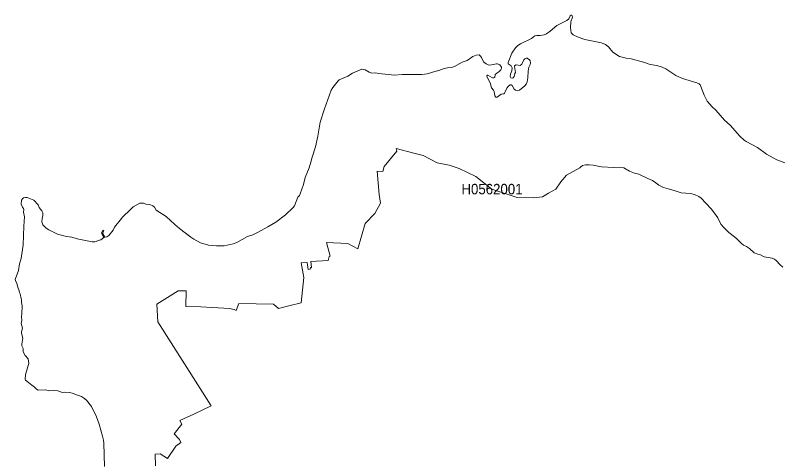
# Model space of a CAD drawing. Extents: x 369010 to 739155, y 6377141 to 6616555.
# Drawn here: x 484601 to 491944, y 6568141 to 6572404 of the extents above; entities that cross this region are included whole.
import ezdxf
from ezdxf.enums import TextEntityAlignment as Align

# ---------------------------------------------------------------- set-up
doc = ezdxf.new("R2010")
doc.units = 0
doc.header["$LTSCALE"] = 40
doc.layers.add('1', color=7, linetype='Continuous', lineweight=13)
doc.layers.add('2', color=7, linetype='Continuous')

msp = doc.modelspace()

# ---------------------------------------------------------------- linework, layer by layer
at = {"layer": '1'}
for points in [[(491209.75, 6571638.8), (491179.46, 6571721.55), (491170.86, 6571737.77), (491161.92, 6571745.39), (491138.92, 6571756.64), (491001.38, 6571798.68), (490938.33, 6571827.97), (490840.84, 6571891.03), (490806.42, 6571907.91), (490754.78, 6571922.31), (490691.72, 6571932.08), (490628.67, 6571955.74), (490508.35, 6571987.85), (490462.5, 6571994.31), (490399.28, 6572009.53), (490335.06, 6572050.91), (490293.03, 6572102.54), (490264.23, 6572124.56), (490224.18, 6572139.78), (490063.64, 6572173.22), (490000.58, 6572194.9), (489953.41, 6572216.25), (489934.05, 6572237.6), (489927.26, 6572287.91), (489932.39, 6572340.71), (489946.13, 6572387.21), (489945.14, 6572400.62), (489941, 6572404.42), (489934.38, 6572404.42), (489925.77, 6572398.47), (489910.38, 6572370.99), (489892.84, 6572353.45), (489796.35, 6572306.94), (489732.3, 6572251.66), (489696.05, 6572226.67), (489674.37, 6572218.07), (489636.14, 6572211.12), (489605.52, 6572211.12), (489585.5, 6572206.65), (489552.73, 6572183.48), (489446.97, 6572130.52), (489421.81, 6572113.3), (489399.8, 6572092.61), (489366.37, 6572040.15), (489328.8, 6571950.28), (489330.45, 6571938.86), (489357.43, 6571919.99), (489367.03, 6571901.79), (489364.22, 6571871.34), (489352.13, 6571840.72), (489348.49, 6571817.71), (489356.44, 6571805.3), (489369.02, 6571801.49), (489378.78, 6571803.15), (489388.71, 6571817.71), (489394.67, 6571845.19), (489398.81, 6571855.94), (489390.2, 6571914.53), (489391.86, 6571918.34), (489404.93, 6571930.26), (489445.31, 6571923.8), (489460.71, 6571936.54), (489478.91, 6571976.76), (489489.01, 6571985.86), (489501.75, 6571991.99), (489512.34, 6571991.66), (489535.18, 6571977.09), (489540.64, 6571967.49), (489543.79, 6571947.96), (489539.65, 6571930.92), (489527.9, 6571906.92), (489521.45, 6571867.53), (489517.97, 6571804.31), (489510.69, 6571764.59), (489501.42, 6571745.22), (489489.01, 6571728.84), (489439.69, 6571686.8), (489415.69, 6571681.17), (489398.81, 6571685.97), (489388.38, 6571695.74), (489369.18, 6571732.15), (489358.42, 6571737.77), (489348.16, 6571737.44), (489328.14, 6571721.89), (489318.04, 6571706.99), (489302.32, 6571669.09), (489293.71, 6571656.35)], [(489293.71, 6571656.35), (489287.42, 6571651.88), (489264.09, 6571648.9), (489225.03, 6571619.27), (489210.3, 6571620.6), (489200.7, 6571631.69), (489195.73, 6571672.23), (489188.95, 6571685.64), (489168.59, 6571710.13), (489157.17, 6571756.31), (489124.57, 6571817.71), (489124.57, 6571822.84), (489130.36, 6571830.79), (489136.15, 6571831.12), (489179.68, 6571804.64), (489193.42, 6571803.48), (489200.2, 6571806.95), (489206.49, 6571837.24), (489220.23, 6571849.99), (489240.59, 6571860.74), (489259.45, 6571880.44), (489265.74, 6571893.02), (489266.07, 6571906.26), (489248.53, 6571928.93), (489227.84, 6571937.87), (489216.42, 6571938.86), (489154.52, 6571926.45), (489137.31, 6571929.92), (489119.93, 6571938.86), (489091.8, 6571958.89), (489073.1, 6572000.59), (489063.16, 6572014), (489050.75, 6572023.77), (489022.78, 6572021.28), (488992.16, 6572008.21), (488934.73, 6571972.29), (488888.56, 6571953.43), (488814.08, 6571913.04), (488784.46, 6571902.12), (488746.22, 6571898.98), (488714.94, 6571892.69), (488664.63, 6571875.14), (488626.4, 6571866.87), (488553.91, 6571842.54), (488502.93, 6571835.26), (488313.1, 6571836.91), (488238.46, 6571830.79), (488088.84, 6571845.85), (488059.55, 6571851.48), (488022.48, 6571850.81), (487995.5, 6571858.26), (487957.6, 6571879.94), (487925.16, 6571886.23), (487835.62, 6571848), (487790.11, 6571821.52), (487708.85, 6571784.94), (487699.25, 6571777.33), (487646.78, 6571711.29), (487632.71, 6571685.97), (487567.34, 6571506.23), (487527.62, 6571378.8), (487503.62, 6571245.07), (487479.79, 6571143.12), (487448.01, 6571042.82), (487436.43, 6570994), (487419.88, 6570940.54), (487382.64, 6570848.85), (487366.09, 6570780), (487335.47, 6570690.13), (487327.86, 6570676.23), (487312.3, 6570658.36), (487280.69, 6570577.43), (487266.45, 6570559.05), (487193.14, 6570490.21), (487099.46, 6570420.36), (487024.98, 6570373.86), (486925.18, 6570319.4), (486880.99, 6570299.71), (486827.54, 6570282.17), (486727.41, 6570226.06), (486690.5, 6570211.83), (486606.42, 6570192.96), (486533.11, 6570191.97), (486455.98, 6570197.76), (486379.02, 6570222.59), (486314.64, 6570257.01), (486284.02, 6570277.04), (486176.44, 6570359.62), (486130.27, 6570397.19), (486049.67, 6570472.99), (485953.18, 6570535.72), (485935.3, 6570562.53), (485922.23, 6570576.1), (485891.61, 6570588.35), (485853.38, 6570592.98), (485830.54, 6570601.26), (485794.79, 6570601.26), (485731.07, 6570568.16), (485707.24, 6570539.86), (485628.79, 6570467.53)], [(491982.49, 6570988.7), (491907.85, 6571016.67), (491807.55, 6571073.44), (491721.82, 6571135.17), (491612.26, 6571192.44), (491593.89, 6571205.84), (491553.67, 6571244.08), (491459.33, 6571350.16), (491406.54, 6571398.66), (491323.12, 6571493.16), (491288.04, 6571525.1), (491239.87, 6571582.03), (491209.75, 6571638.8)], [(485947.55, 6568082.29), (485944.41, 6568193.01), (485989.59, 6568196.15), (486061.92, 6568151.14), (486139.87, 6568269.31), (486189.52, 6568307.37), (486177.77, 6568335.01), (486126.13, 6568390.46), (486200.28, 6568481.48), (486181.24, 6568517.07), (486315.47, 6568578.47), (486481.14, 6568656.42), (485969.07, 6569462.59), (485958.64, 6569632.73), (486163.04, 6569761.49), (486241.98, 6569761.49), (486237.18, 6569610.05), (486382.5, 6569607.9), (486656.9, 6569590.53), (486702.25, 6569580.43), (486719.13, 6569570.83), (486747.27, 6569638.02), (487078.94, 6569633.23), (487125.11, 6569590.53), (487237.82, 6569621.64), (487344.9, 6569645.47), (487370.06, 6569888.43), (487343.58, 6570028.28), (487401.67, 6570033.08), (487412.26, 6569966.22), (487436.43, 6569970.69), (487433.94, 6569985.58), (487442.55, 6569986.41), (487437.42, 6570042.02), (487603.25, 6570050.46), (487611.03, 6570091.34), (487621.96, 6570093.49), (487586.21, 6570224.24), (487791.93, 6570214.48), (487888.09, 6570164.33), (487957.76, 6570407.29), (488049.12, 6570501.96), (488104.57, 6570603.58), (488091.99, 6570686.33), (488074.44, 6570909.43), (488126.41, 6570905.95), (488139.65, 6570954.44), (488260.31, 6571101.25), (488254.84, 6571127.73), (488424.15, 6571083.37), (488513.2, 6571057.88), (488650.07, 6570988.7), (488763.93, 6570966.86), (488859.59, 6570935.41), (489019.97, 6570856.8), (489174.38, 6570737.14), (489414.7, 6570655.71), (489569.11, 6570652.56), (489657.49, 6570663.32), (489715.25, 6570698.08), (489787.08, 6570736.14), (489833.75, 6570805.99), (489890.68, 6570870.04), (490015.64, 6570942.53), (490024.74, 6570947), (490043.61, 6570962.06), (490071.58, 6570969.84), (490107.33, 6570970.99), (490145.4, 6570965.7), (490223.51, 6570949.98), (490341.85, 6570943.69), (490409.87, 6570946.83), (490439.17, 6570940.04), (490492.13, 6570909.1)], [(491965.77, 6569988.4), (491936.98, 6570014.05), (491905.03, 6570050.13), (491885.01, 6570065.36), (491862, 6570075.29), (491785.04, 6570086.38), (491742.67, 6570108.39), (491724.8, 6570113.52), (491690.21, 6570125.6), (491645.69, 6570166.98), (491617.55, 6570184.85), (491588.76, 6570197.92), (491565.09, 6570216.79), (491526.36, 6570256.51), (491500.71, 6570278.03), (491447.25, 6570320.89), (491394.45, 6570370.71), (491373.93, 6570395.87), (491357.71, 6570426.82), (491340, 6570461.41), (491323.78, 6570482.26), (491281.75, 6570543), (491226.8, 6570601.75), (491182.77, 6570651.41), (491160.27, 6570667.63), (491117.9, 6570685), (491079.17, 6570694.44), (490990.13, 6570700.73), (490942.96, 6570717.44), (490922.6, 6570723.23), (490866, 6570738.46), (490819.99, 6570752.03), (490774.97, 6570773.55), (490746.67, 6570798.7), (490715.72, 6570820.55), (490669.05, 6570839.42), (490584.31, 6570878.81), (490541.28, 6570890.89), (490492.13, 6570909.1), (490439.17, 6570940.04), (490409.87, 6570946.83), (490341.85, 6570943.69), (490223.51, 6570949.98), (490145.4, 6570965.7), (490107.33, 6570970.99), (490071.58, 6570969.84), (490043.61, 6570962.06), (490024.74, 6570947), (490015.64, 6570942.53), (489890.68, 6570870.04), (489833.75, 6570805.99), (489787.08, 6570736.14), (489715.25, 6570698.08), (489657.49, 6570663.32), (489569.11, 6570652.56), (489414.7, 6570655.71), (489174.38, 6570737.14), (489019.97, 6570856.8), (488859.59, 6570935.41), (488763.93, 6570966.86), (488650.07, 6570988.7), (488513.2, 6571057.88), (488424.15, 6571083.37), (488254.84, 6571127.73), (488260.31, 6571101.25), (488139.65, 6570954.44), (488126.41, 6570905.95), (488074.44, 6570909.43), (488091.99, 6570686.33), (488104.57, 6570603.58), (488049.12, 6570501.96), (487957.76, 6570407.29), (487888.09, 6570164.33)], [(490492.13, 6570909.1), (490541.28, 6570890.89), (490584.31, 6570878.81), (490669.05, 6570839.42), (490715.72, 6570820.55), (490746.67, 6570798.7), (490774.97, 6570773.55), (490819.99, 6570752.03), (490866, 6570738.46), (490922.6, 6570723.23), (490942.96, 6570717.44), (490990.13, 6570700.73), (491079.17, 6570694.44), (491117.9, 6570685), (491160.27, 6570667.63), (491182.77, 6570651.41), (491226.8, 6570601.75), (491281.75, 6570543), (491323.78, 6570482.26), (491340, 6570461.41), (491357.71, 6570426.82), (491373.93, 6570395.87), (491394.45, 6570370.71), (491447.25, 6570320.89), (491500.71, 6570278.03), (491526.36, 6570256.51), (491565.09, 6570216.79), (491588.76, 6570197.92), (491617.55, 6570184.85), (491645.69, 6570166.98), (491690.21, 6570125.6), (491724.8, 6570113.52), (491742.67, 6570108.39), (491785.04, 6570086.38), (491862, 6570075.29), (491885.01, 6570065.36), (491905.03, 6570050.13), (491936.98, 6570014.05), (491965.77, 6569988.4)], [(485628.79, 6570467.53), (485620.02, 6570455.95), (485554.15, 6570373.36), (485538.92, 6570342.91), (485499.7, 6570291.27), (485481, 6570279.52), (485459.81, 6570277.04), (485438.79, 6570314.27), (485449.39, 6570337.94), (485441.11, 6570342.08), (485429.52, 6570312.78), (485451.87, 6570272.9), (485423.4, 6570251.55), (485394.77, 6570244.27), (485378.22, 6570235.33), (485363.82, 6570231.85), (485338, 6570232.68), (485194.18, 6570260.15), (485142.71, 6570275.38), (485091.07, 6570281.17), (485006.5, 6570304.34), (484923.74, 6570344.73), (484898.26, 6570362.93), (484866.81, 6570394.71), (484856.55, 6570423.01), (484858.7, 6570453.63), (484865.49, 6570482.26), (484864.16, 6570510.56), (484855.56, 6570529.26), (484831.72, 6570560.54), (484821.79, 6570586.86), (484778.93, 6570630.22), (484714.88, 6570657.86), (484697.67, 6570657.53), (484680.95, 6570652.56), (484670.03, 6570643.96), (484662.08, 6570630.55), (484658.61, 6570592.98), (484669.2, 6570562.7), (484679.3, 6570550.94), (484681.78, 6570542.01), (484680.29, 6570516.69), (484688.23, 6570472), (484681.78, 6570382.96), (484676.15, 6570203.39), (484656.62, 6570071.65), (484642.06, 6570020.17), (484632.46, 6569957.12), (484601.34, 6569871.22), (484601.67, 6569859.8), (484616.24, 6569831.17), (484625.84, 6569796.74), (484639.74, 6569762.32), (484643.05, 6569744.61), (484648.68, 6569733.69), (484656.12, 6569687.35), (484661.09, 6569674.6), (484659.93, 6569649.11), (484667.88, 6569617.34), (484668.7, 6569598.14), (484662.74, 6569559.91), (484665.23, 6569540.87), (484662.08, 6569515.39), (484663.41, 6569477.16), (484658.28, 6569446.7), (484669.36, 6569404), (484661.09, 6569367.76), (484661.75, 6569355.68), (484674.16, 6569306.69), (484664.9, 6569250.08), (484665.23, 6569234.69), (484676.48, 6569206.39), (484676.48, 6569179.41), (484679.96, 6569167.83), (484695.51, 6569139.2), (484723.48, 6569107.42), (484731.43, 6569064.72), (484700.31, 6568957.31), (484697.17, 6568911.46), (484699.65, 6568903.52), (484728.62, 6568882.5), (484758.57, 6568854.69), (484783.07, 6568839.8), (484803.42, 6568818.12), (484821.3, 6568808.35), (484888, 6568811.5), (484933.84, 6568801.57), (484968.27, 6568804.22), (485008.32, 6568801.57), (485054.82, 6568785.35), (485077.66, 6568788.49), (485123.51, 6568787), (485157.93, 6568777.07), (485197.32, 6568759.03), (485237.54, 6568746.95), (485254.92, 6568735.7), (485283.22, 6568710.54), (485332.7, 6568651.79), (485379.38, 6568551.16), (485406.52, 6568482.48)], [(487888.09, 6570164.33), (487791.93, 6570214.48), (487586.21, 6570224.24), (487621.96, 6570093.49), (487611.03, 6570091.34), (487603.25, 6570050.46), (487437.42, 6570042.02), (487442.55, 6569986.41), (487433.94, 6569985.58), (487436.43, 6569970.69), (487412.26, 6569966.22), (487401.67, 6570033.08), (487343.58, 6570028.28), (487370.06, 6569888.43), (487344.9, 6569645.47), (487237.82, 6569621.64), (487125.11, 6569590.53), (487078.94, 6569633.23), (486747.27, 6569638.02), (486719.13, 6569570.83), (486702.25, 6569580.43), (486656.9, 6569590.53), (486382.5, 6569607.9), (486237.18, 6569610.05), (486241.98, 6569761.49), (486163.04, 6569761.49), (485958.64, 6569632.73), (485969.07, 6569462.59), (486481.14, 6568656.42), (486315.47, 6568578.47), (486181.24, 6568517.07), (486200.28, 6568481.48), (486126.13, 6568390.46), (486177.77, 6568335.01), (486189.52, 6568307.37), (486139.87, 6568269.31), (486061.92, 6568151.14), (485989.59, 6568196.15), (485944.41, 6568193.01), (485947.55, 6568082.29)], [(485406.52, 6568482.48), (485438.96, 6568367.78), (485446.9, 6568327.73), (485450.05, 6568299.1), (485456.67, 6568075.67)]]:
    msp.add_lwpolyline(points, dxfattribs=at)

# ---------------------------------------------------------------- texts
at = {"layer": '2', "width": 0.95}
msp.add_text('H0562001', height=100, dxfattribs=at).set_placement((489174.38, 6570687.14), align=Align.CENTER)

doc.saveas('drawing.dxf')
